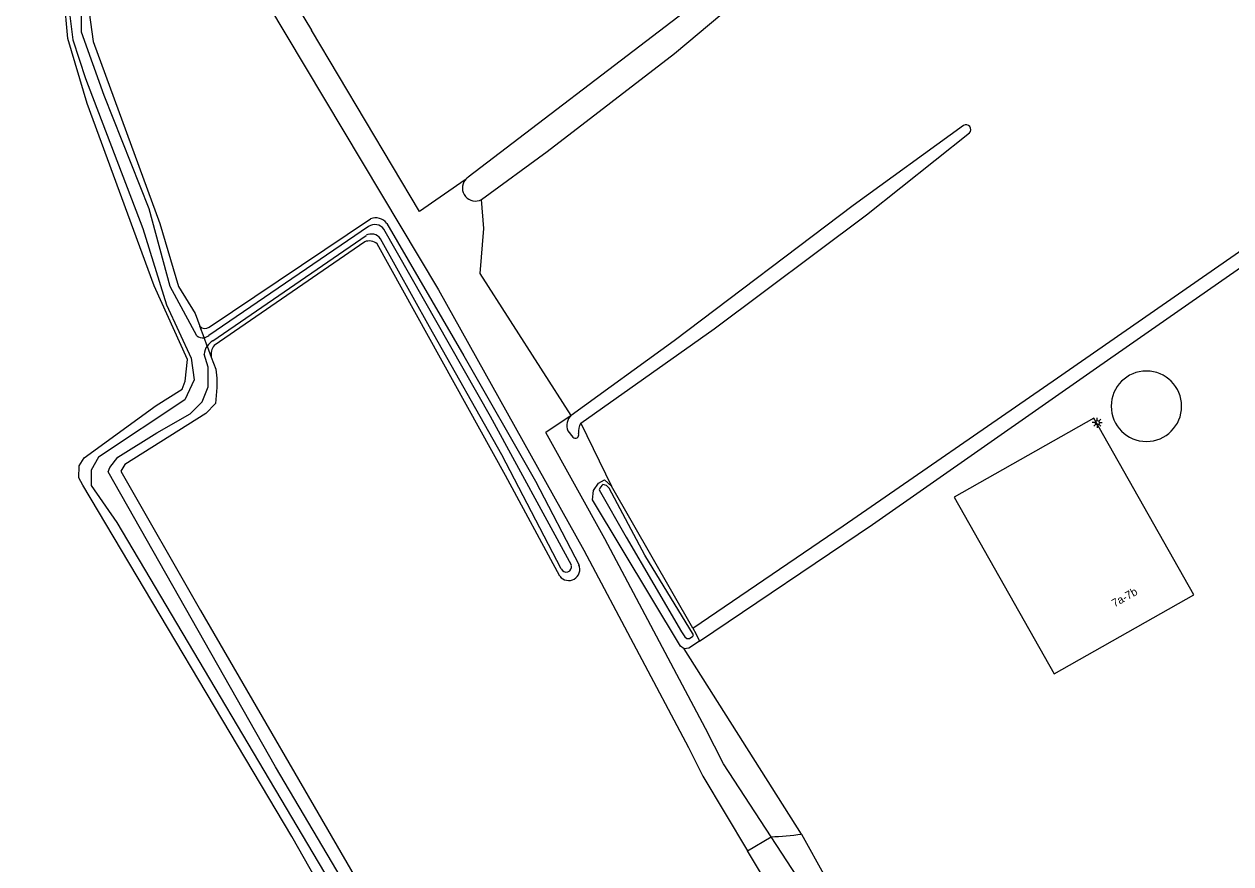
# Model space of a CAD drawing. Extents: x 137000 to 140001, y 403500 to 406000.
# Drawn here: x 139693.7 to 139844.4, y 404094.1 to 404199.1 of the extents above; entities that cross this region are included whole.
import ezdxf

# ---------------------------------------------------------------- set-up
doc = ezdxf.new("R2010")
doc.units = 0
for name, color, linetype in [('gg-afsc-erfafscheiding', 7, 'Continuous'), ('gg-anno-huisnummerreeks BGT', 7, 'Continuous'), ('gg-bbg-hoofdgebouw', 7, 'Continuous'), ('gg-bbg-opslagtank', 7, 'Continuous'), ('gg-knt-bronhoudergrens', 7, 'Continuous'), ('gg-knt-verharding', 7, 'Continuous'), ('gg-knt-verharding nz', 7, 'Continuous'), ('gg-kntw-bovenkant insteek waterloop', 7, 'Continuous'), ('gg-kntw-waterlijn', 7, 'Continuous'), ('gt-grn-groengrens', 7, 'Continuous'), ('gt-grn-vlakafsluiter', 7, 'Continuous'), ('gt-symb-lichtmast', 7, 'Continuous')]:
    doc.layers.add(name, color=color, linetype=linetype)

# ---------------------------------------------------------------- blocks, each defined once
blk = doc.blocks.new('gt0-LMAST')
at = {"layer": 'gt-symb-lichtmast'}
for p, q in [((-0.18, 0.17), (-0.45, 0.44)), ((-0.01, 0.25), (-0.01, 0.62)), ((0.17, 0.17), (0.44, 0.44)), ((-0.26, 0), (-0.63, 0)), ((-0.18, -0.18), (-0.45, -0.45)), ((-0.01, -0.25), (-0.01, -0.63)), ((0.44, -0.45), (0.17, -0.18)), ((0.24, 0), (0.62, 0))]:
    blk.add_line(p, q, dxfattribs=at)
blk.add_circle((-0.01, 0), 0.25, dxfattribs=at)

msp = doc.modelspace()

# ---------------------------------------------------------------- linework, layer by layer
at = {"layer": 'gg-afsc-erfafscheiding'}
msp.add_line((139790.81, 404097.86), (139776.15, 404121.02), dxfattribs=at)
at = {"layer": 'gg-bbg-hoofdgebouw'}
msp.add_lwpolyline([(139822.36, 404117.88), (139839.81, 404127.77), (139827.32, 404149.82), (139809.85, 404139.95), (139822.36, 404117.88)], dxfattribs=at)
at = {"layer": 'gg-bbg-opslagtank'}
for start, end in [(90, 270), (270, 90)]:
    msp.add_arc((139833.89, 404151.33), 4.4, start, end, dxfattribs=at)
at = {"layer": 'gg-knt-bronhoudergrens'}
for p in [(139727.93, 404201.05), (139743.08, 404175.68)]:
    msp.add_line(p, (139729.56, 404198.33), dxfattribs=at)
msp.add_lwpolyline([(139762.03, 404150.19), (139750.63, 404167.92), (139751.09, 404173.54), (139750.83, 404177.15)], dxfattribs=at)
at = {"layer": 'gg-knt-verharding'}
for p, q in [((139784.04, 404095.78), (139786.99, 404097.54)), ((139790.81, 404097.86), (139793.76, 404092.51))]:
    msp.add_line(p, q, dxfattribs=at)
msp.add_lwpolyline([(139800.27, 404065.41), (139788.99, 404087.52), (139784.04, 404095.78)], dxfattribs=at)
msp.add_arc((139785.82, 404133.81), 36.29, 271.8354, 277.8905, dxfattribs=at)
at = {"layer": 'gg-knt-verharding nz'}
msp.add_lwpolyline([(139792.64, 404088.79), (139792.26, 404089.47), (139786.99, 404097.54)], dxfattribs=at)
at = {"layer": 'gg-kntw-bovenkant insteek waterloop'}
for p, q in [((139716.79, 404161.21), (139736.96, 404174.73)), ((139736.22, 404171.88), (139717.43, 404158.92)), ((139716.15, 404159.9), (139715.61, 404161.34)), ((139716.54, 404158.85), (139717.05, 404157.47)), ((139761.62, 404148.26), (139762.23, 404147.45)), ((139777.24, 404123.6), (139767.07, 404141.34))]:
    msp.add_line(p, q, dxfattribs=at)
for points in [[(139692.69, 404244.55), (139693.9, 404245.86), (139695.29, 404246.63), (139696.38, 404246.51), (139700.02, 404240.43), (139700.3, 404239.07), (139699.34, 404236.51), (139697.06, 404231.3), (139697.14, 404230.34), (139704.33, 404213.32), (139704.45, 404212.53), (139701.8, 404200.53), (139702.31, 404196.92), (139710.64, 404174.18), (139712.97, 404166.3), (139715.03, 404162.9), (139715.61, 404161.34)], [(139810.86, 404228.05), (139805.46, 404223.73), (139775.36, 404199.93), (139749.16, 404179.94)], [(139750.83, 404177.15), (139759.02, 404183.15), (139774.93, 404195.42), (139793.95, 404211.4), (139812.11, 404226.79)], [(139777.24, 404123.6), (139796.02, 404136.4), (139822.77, 404154.86), (139854.51, 404176.9), (139882.82, 404196.33), (139904.39, 404211.07), (139912.76, 404216.98)], [(139692.2, 404039.73), (139693.87, 404041.36), (139699.64, 404046), (139701.97, 404047.42), (139712.14, 404059.58), (139728.53, 404081.25), (139732.17, 404086.41), (139732.55, 404087.62), (139732.43, 404088.22), (139727.11, 404097.56), (139701.01, 404141.46), (139700.5, 404142.39), (139700.55, 404143.88), (139701.19, 404144.89), (139710.19, 404151.43), (139713.42, 404153.46), (139713.79, 404154.48), (139714.09, 404157.18), (139709.9, 404166.37), (139701.55, 404189.15), (139699.12, 404197.27), (139698.66, 404202.42)], [(139811.04, 404186.42), (139797.25, 404176.4), (139774.88, 404159.5), (139762.03, 404150.19)], [(139763.24, 404149.21), (139779.9, 404161.02), (139798.92, 404175.25), (139811.79, 404185.49)], [(139778.07, 404121.99), (139799.67, 404136.56), (139827.67, 404156.11), (139856.76, 404176.41), (139870.28, 404185.61)], [(139738.99, 404174.18), (139748.63, 404157.62), (139757.57, 404141.96), (139763, 404131.48)], [(139760.59, 404130.09), (139753.8, 404142.69), (139737.8, 404171.63)], [(139717.05, 404157.47), (139717.61, 404155.98), (139717.76, 404154.82), (139717.77, 404153.66), (139717.58, 404151.65), (139716.37, 404150.42), (139706.26, 404144.03), (139705.75, 404143.21), (139715.7, 404125.82), (139735.64, 404091.41), (139736.82, 404088.85), (139736.97, 404087.49), (139736.55, 404085.85), (139735.97, 404084.57), (139722.37, 404067.51), (139706.21, 404046.33), (139703.34, 404043.54), (139699.88, 404041.54), (139697.68, 404040.18), (139696.61, 404038.95), (139688.52, 404026.4)], [(139776.15, 404121.02), (139775.66, 404121.33), (139764.7, 404139.64), (139764.8, 404140.78), (139765.44, 404141.7), (139766.18, 404142.12), (139767.07, 404141.34)], [(139778.07, 404121.99), (139776.74, 404121.1), (139776.15, 404121.02)]]:
    msp.add_lwpolyline(points, dxfattribs=at)
for centre, radius, start, end in [((139811.35, 404185.9), 0.607, 316.4444, 121.009), ((139750.06, 404178.59), 1.63, 141.5593, 298.0149), ((139750.05, 404178.6), 1.61, 123.8795, 141.734), ((139737.61, 404173.14), 1.72, 37.1056, 112.513), ((139736.79, 404170.34), 1.64, 51.9436, 110.1932), ((139716.28, 404162), 0.946, 224.9615, 302.6566), ((139718.81, 404157.79), 1.79, 140.7386, 190.2062), ((139763.19, 404148.94), 1.71, 132.7726, 203.4232), ((139764.62, 404148.22), 1.7, 144.0503, 190.4094), ((139762.53, 404147.77), 0.439, 226.6146, 18.565), ((139761.7, 404130.95), 1.4, 217.7403, 22.5827)]:
    msp.add_arc(centre, radius, start, end, dxfattribs=at)
at = {"layer": 'gg-kntw-waterlijn'}
for p, q in [((139736.7, 404173.79), (139716.73, 404160.18)), ((139717.27, 404159.49), (139736.39, 404172.68))]:
    msp.add_line(p, q, dxfattribs=at)
for points in [[(139715.27, 404160.12), (139711.91, 404166.28), (139709.31, 404175.98), (139703.67, 404190.15), (139700.85, 404198.07), (139700.87, 404202.19)], [(139699.3, 404200.79), (139699.74, 404197.13), (139701.33, 404192.29), (139708.49, 404173.55), (139711.48, 404163.98), (139714.56, 404157.34), (139714.92, 404154.63), (139713.76, 404152.14), (139702.97, 404144.97), (139702.06, 404143.36), (139702.07, 404141.42), (139705.27, 404136.79), (139733.2, 404089.66), (139734, 404087.57), (139733.68, 404086.09), (139726.09, 404076.17), (139704.59, 404048.5), (139702.35, 404046.26), (139697.03, 404043.03), (139695.29, 404041.28), (139692.89, 404037.32)], [(139762.05, 404131.45), (139751.93, 404150.04), (139738.62, 404173.47)], [(139760.78, 404131), (139753.36, 404145.27), (139744.34, 404161.26), (139738.2, 404172.24)], [(139688.65, 404028.57), (139693.87, 404036.18), (139696.82, 404040.23), (139698.56, 404041.59), (139703.08, 404044.3), (139704.35, 404045.47), (139706.27, 404048.12), (139710.9, 404054.19), (139728.97, 404077.09), (139734.78, 404084.23), (139735.93, 404086.46), (139735.75, 404087.71), (139734.5, 404090.34), (139725.06, 404106.27), (139704.17, 404143.14), (139704.37, 404143.66), (139705.38, 404144.97), (139710.24, 404148), (139714.43, 404150.38), (139715.9, 404151.88), (139716.68, 404153.75), (139716.65, 404156.19), (139716.18, 404157.84)], [(139766.75, 404141.1), (139766.42, 404141.43), (139765.99, 404141.53), (139765.84, 404141.42), (139765.59, 404141.11), (139765.52, 404140.88), (139768.89, 404134.98), (139775.82, 404123.12), (139776.22, 404122.53), (139776.49, 404122.31), (139776.82, 404122.3), (139777.21, 404122.61), (139777.32, 404122.76), (139771.23, 404132.7), (139766.75, 404141.1)], [(139777.24, 404123.6), (139777.59, 404122.93), (139778.07, 404121.99)]]:
    msp.add_lwpolyline(points, dxfattribs=at)
for centre, radius, start, end in [((139737.48, 404172.56), 1.46, 38.7102, 122.2782), ((139737.04, 404171.43), 1.42, 35.0462, 117.3884), ((139715.96, 404161), 1.12, 231.8407, 279.6282), ((139715.97, 404161), 1.12, 279.4153, 313.0001), ((139718.21, 404157.68), 2.04, 145.132, 175.7396), ((139718.21, 404157.68), 2.04, 117.6118, 145.1051), ((139761.39, 404131.28), 0.676, 204.2057, 14.278)]:
    msp.add_arc(centre, radius, start, end, dxfattribs=at)
at = {"layer": 'gt-grn-groengrens'}
for p, q in [((139748.79, 404179.6), (139743.08, 404175.68)), ((139762.03, 404150.19), (139758.84, 404148.04)), ((139763.24, 404149.21), (139767.07, 404141.34))]:
    msp.add_line(p, q, dxfattribs=at)
for points in [[(139625.51, 404362.43), (139646.42, 404326.09), (139675.88, 404279.73), (139697.9, 404245.49), (139745.44, 404165.89), (139763.61, 404133.35), (139776.67, 404108.69), (139778.45, 404105.12), (139784.04, 404095.78)], [(139786.99, 404097.54), (139781.04, 404106.64), (139778.8, 404111.07), (139766.24, 404134.78), (139758.84, 404148.04)]]:
    msp.add_lwpolyline(points, dxfattribs=at)
at = {"layer": 'gt-grn-vlakafsluiter'}
msp.add_line((139716.54, 404158.85), (139716.15, 404159.9), dxfattribs=at)

# ---------------------------------------------------------------- block references
at = {"layer": 'gt-symb-lichtmast'}
msp.add_blockref('gt0-LMAST', (139827.76, 404149.28), dxfattribs=at)

# ---------------------------------------------------------------- texts
at = {"layer": 'gg-anno-huisnummerreeks BGT'}
msp.add_text('7a-7b', height=1, rotation=29.5, dxfattribs=at).set_placement((139829.91, 404126.18))

doc.saveas('drawing.dxf')
